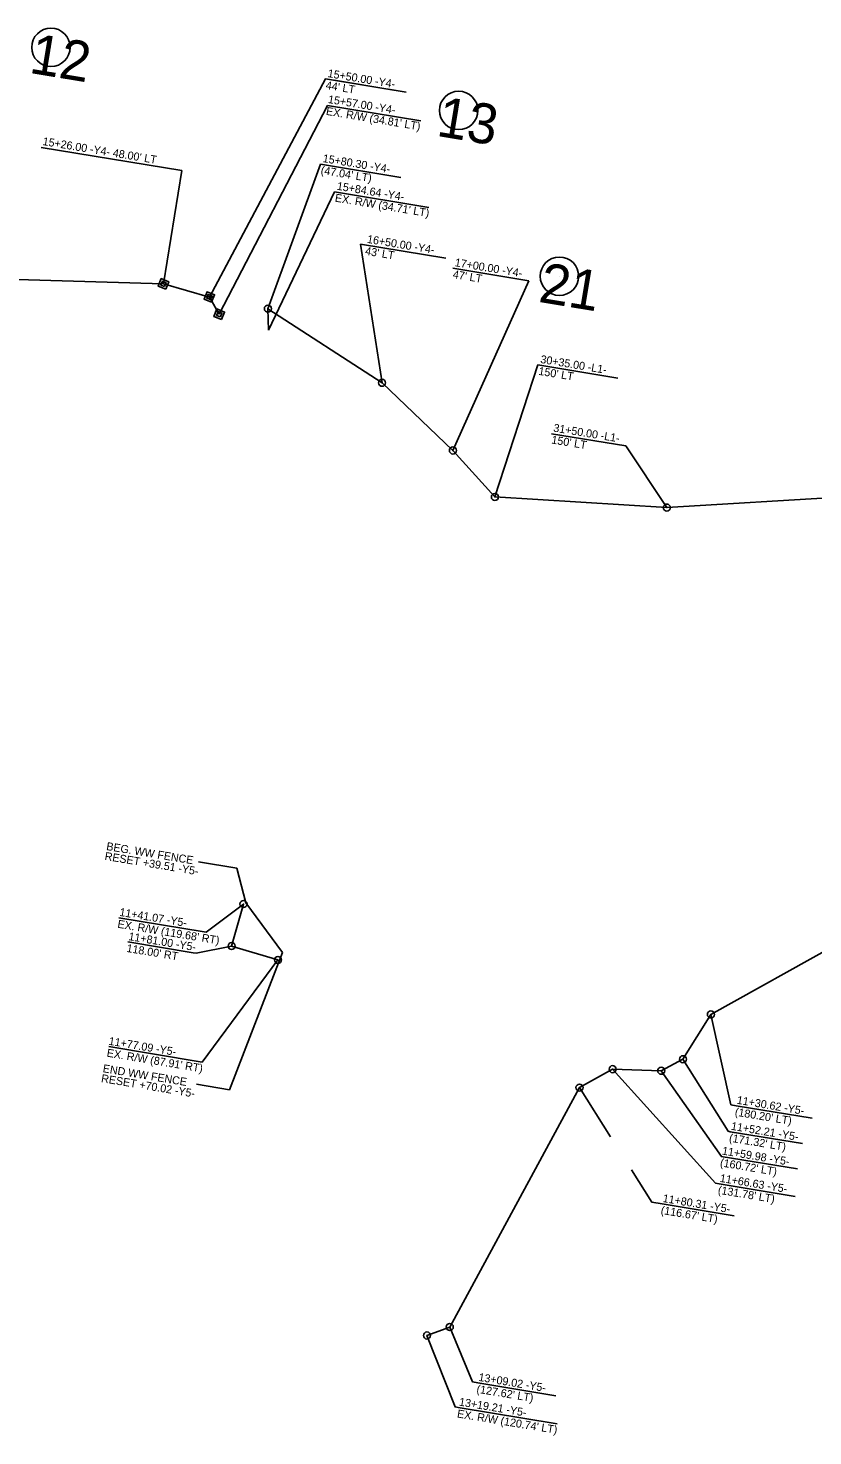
# Model space of a CAD drawing. Extents: x 2175623 to 2194100, y 76458 to 87202.
# Drawn here: x 2192684 to 2193175, y 86276 to 87155 of the extents above; entities that cross this region are included whole.
import ezdxf

# ---------------------------------------------------------------- set-up
doc = ezdxf.new("R2010")
doc.units = 0
for name, color, linetype in [('Exist Property Iron Pin CELL', 7, 'Continuous'), ('Prop Drainage Structure Box Number Symbol CELL', 7, 'Continuous'), ('Prop Drainage Structure Headwall CELL', 7, 'Continuous'), ('Prop Drainage Structure Pipe RCP 36in Class IV', 7, 'Continuous'), ('Prop Drainage Structure Pipe RCP 42in Class IV', 7, 'Continuous'), ('Prop Drainage Structure Pipe RCP 60in Class IV', 7, 'Continuous'), ('Prop Drainage Structure Pipe Removal Label', 7, 'Continuous'), ('Prop Drainage Structure Plot Symbol 50 Scale', 7, 'Continuous'), ('Prop Earthen Structure Base Ditch Special Lateral Detail Label', 7, 'Continuous'), ('Prop Erosion Rip Rap Pad at Outlet Label', 7, 'Continuous'), ('Prop Plan Preparation Crest Label', 7, 'Continuous'), ('Prop Plan Preparation Sag Label', 7, 'Continuous'), ('Scratch_Level_3', 7, 'Continuous')]:
    doc.layers.add(name, color=color, linetype=linetype)

# ---------------------------------------------------------------- blocks, each defined once
blk = doc.blocks.new('ROW Marker Permanent Easement-E')
at = {"layer": 'Prop Earthen Structure Base Ditch Special Lateral Detail Label'}
for points in [[(0, 0.072), (0.072, 0), (0, -0.072), (-0.072, 0)], [(0, 0.036), (0.036, 0), (0, -0.036), (-0.036, 0)]]:
    blk.add_lwpolyline(points, close=True, dxfattribs=at)
at = {"layer": 'Prop Plan Preparation Crest Label'}
blk.add_line((0, 0), (0, 0), dxfattribs=at)

msp = doc.modelspace()

# ---------------------------------------------------------------- linework, layer by layer
at = {"layer": 'Exist Property Iron Pin CELL'}
for centre, radius in [((2192834.02, 86980.16), 2.2), ((2192834.02, 86980.16), 0.0707), ((2192905.37, 86933.87), 2.2), ((2192905.37, 86933.87), 0.0707), ((2192949.62, 86891.57), 2.2), ((2192949.62, 86891.57), 0.0707), ((2192975.84, 86862.52), 2.2), ((2192975.84, 86862.52), 0.0707), ((2193083.29, 86855.91), 2.2), ((2193083.29, 86855.91), 0.0707), ((2192818.79, 86608.21), 2.2), ((2192818.79, 86608.21), 0.0707), ((2192811.36, 86581.93), 2.2), ((2192811.36, 86581.93), 0.0707), ((2192840.31, 86573.26), 2.2), ((2192840.31, 86573.26), 0.0707), ((2193110.8, 86539.2), 2.2), ((2193110.8, 86539.2), 0.0707), ((2193093.38, 86511.25), 2.2), ((2193093.38, 86511.25), 0.0707), ((2193049.41, 86505.02), 2.2), ((2193049.41, 86505.02), 0.0707), ((2193079.77, 86504), 2.2), ((2193079.77, 86504), 0.0707), ((2193028.73, 86493.51), 2.2), ((2193028.73, 86493.51), 0.0707), ((2192947.69, 86343.91), 2.2), ((2192947.69, 86343.91), 0.0707), ((2192933.44, 86338.61), 2.2), ((2192933.44, 86338.61), 0.0707)]:
    msp.add_circle(centre, radius, dxfattribs=at)
at = {"layer": 'Prop Drainage Structure Box Number Symbol CELL'}
for p, q in [((2192698.47, 87143.44), (2192698.47, 87143.44)), ((2192953.24, 87104.02), (2192953.24, 87104.02)), ((2193016.2, 87000.44), (2193016.2, 87000.44))]:
    msp.add_line(p, q, dxfattribs=at)
for centre in [(2192698.47, 87143.44), (2192953.24, 87104.02), (2193016.2, 87000.44)]:
    msp.add_circle(centre, 12, dxfattribs=at)
at = {"layer": 'Prop Drainage Structure Headwall CELL'}
for p, q in [((2192912.8, 87116.74), (2192875.39, 87122.94)), ((2192803.63, 86976.67), (2192871.23, 87107.21)), ((2192929.62, 87097.54), (2192871.23, 87107.21)), ((2192780.26, 87066.4), (2192692.37, 87080.97))]:
    msp.add_line(p, q, dxfattribs=at)
for points in [[(2192920.43, 87115.48), (2192870.05, 87123.83), (2192797.46, 86987.46)], [(2192692.37, 87080.97), (2192780.26, 87066.4), (2192768.82, 86995.61)]]:
    msp.add_lwpolyline(points, dxfattribs=at)
at = {"layer": 'Prop Drainage Structure Pipe RCP 36in Class IV'}
for p, q in [((2192834.02, 86980.16), (2192866.85, 87070.48)), ((2192866.85, 87070.48), (2192917.03, 87062.17)), ((2192834.5, 86966.77), (2192875.68, 87053.18)), ((2192875.68, 87053.18), (2192934.6, 87043.42)), ((2192891.89, 87020.46), (2192945.19, 87011.63)), ((2192905.37, 86933.87), (2192891.89, 87020.46)), ((2192949.56, 87005.38), (2192997.1, 86997.5)), ((2192949.62, 86891.57), (2192997.1, 86997.5)), ((2192975.84, 86862.52), (2193002.6, 86945)), ((2193052.71, 86936.7), (2193002.6, 86945)), ((2193057.66, 86894.43), (2193011.27, 86902.02)), ((2193083.29, 86855.91), (2193057.66, 86894.43)), ((2193174.09, 86474.35), (2193126.55, 86482.21)), ((2193168.13, 86458.49), (2193122.95, 86465.96)), ((2193164.86, 86442.65), (2193117.31, 86450.52)), ((2193163.49, 86425.55), (2193115.95, 86433.41)), ((2193125.45, 86413.34), (2193080.27, 86420.81)), ((2193013.87, 86301), (2192965.15, 86309.07)), ((2193014.7, 86283.43), (2192952.99, 86293.65))]:
    msp.add_line(p, q, dxfattribs=at)
for points in [[(2193126.55, 86482.21), (2193123.29, 86482.75), (2193110.8, 86539.2)], [(2193122.95, 86465.96), (2193121.54, 86466.2), (2193093.38, 86511.25)], [(2193115.95, 86433.41), (2193113.6, 86433.8), (2193049.41, 86505.02)], [(2193117.31, 86450.52), (2193117.49, 86450.49), (2193079.77, 86504)], [(2193048.1, 86462.81), (2193028.73, 86493.51)], [(2193080.27, 86420.81), (2193073.92, 86421.86), (2193061.13, 86442.15)], [(2192965.15, 86309.07), (2192961.89, 86309.61), (2192947.69, 86343.91)], [(2192952.99, 86293.65), (2192950.97, 86293.99), (2192933.44, 86338.61)]]:
    msp.add_lwpolyline(points, dxfattribs=at)
at = {"layer": 'Prop Drainage Structure Pipe RCP 42in Class IV'}
for p, q in [((2192818.79, 86608.21), (2192811.36, 86581.93)), ((2192811.36, 86581.93), (2192840.31, 86573.26))]:
    msp.add_line(p, q, dxfattribs=at)
at = {"layer": 'Prop Drainage Structure Pipe RCP 60in Class IV'}
for p, q in [((2192794.17, 86590.79), (2192740.81, 86599.63)), ((2192787.42, 86577.7), (2192746.5, 86584.48)), ((2192791.68, 86509.68), (2192734.6, 86519.14))]:
    msp.add_line(p, q, dxfattribs=at)
for points in [[(2192794.17, 86590.79), (2192795.48, 86590.57), (2192818.79, 86608.21)], [(2192787.42, 86577.7), (2192789.13, 86577.42), (2192811.36, 86581.93)], [(2192791.68, 86509.68), (2192792.96, 86509.46), (2192840.31, 86573.26)]]:
    msp.add_lwpolyline(points, dxfattribs=at)
at = {"layer": 'Prop Drainage Structure Pipe Removal Label'}
for p, q in [((2192814.59, 86630.64), (2192790.68, 86634.61)), ((2192820.2, 86608.91), (2192814.59, 86630.64)), ((2192843.22, 86577.94), (2192810.12, 86492.12)), ((2192810.12, 86492.12), (2192789.43, 86495.55))]:
    msp.add_line(p, q, dxfattribs=at)
at = {"layer": 'Prop Drainage Structure Plot Symbol 50 Scale'}
for p, q in [((2192677.31, 86998.39), (2192768.82, 86995.61)), ((2192768.82, 86995.61), (2192797.46, 86987.46)), ((2192797.46, 86987.46), (2192803.63, 86976.67))]:
    msp.add_line(p, q, dxfattribs=at)
at = {"layer": 'Prop Plan Preparation Sag Label'}
for p, q in [((2192834.02, 86980.16), (2192905.37, 86933.87)), ((2192834.5, 86966.77), (2192834.02, 86980.16)), ((2192905.37, 86933.87), (2192949.62, 86891.57)), ((2192949.62, 86891.57), (2192975.84, 86862.52)), ((2192975.84, 86862.52), (2193083.29, 86855.91)), ((2193083.29, 86855.91), (2193237.41, 86865.08)), ((2193110.8, 86539.2), (2193189.2, 86582.84)), ((2193093.38, 86511.25), (2193110.8, 86539.2)), ((2193079.77, 86504), (2193093.38, 86511.25)), ((2193028.73, 86493.51), (2193049.41, 86505.02)), ((2193049.41, 86505.02), (2193079.77, 86504)), ((2192947.69, 86343.91), (2193028.73, 86493.51)), ((2192933.44, 86338.61), (2192947.69, 86343.91))]:
    msp.add_line(p, q, dxfattribs=at)
at = {"layer": 'Scratch_Level_3'}
msp.add_line((2192820.2, 86608.91), (2192843.22, 86577.94), dxfattribs=at)

# ---------------------------------------------------------------- block references
at = {"layer": 'Prop Plan Preparation Sag Label', "xscale": 49.99999999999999, "yscale": 50.00000000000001, "rotation": -156.87942851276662}
for p in [(2192768.82, 86995.61), (2192797.46, 86987.46), (2192803.63, 86976.67)]:
    msp.add_blockref('ROW Marker Permanent Easement-E', p, dxfattribs=at)

# ---------------------------------------------------------------- texts
at = {"layer": 'Prop Drainage Structure Headwall CELL'}
for s, p in [('15+50.00 -Y4-', (2192871.12, 87124.92)), ("44' LT", (2192869.9, 87117.52)), ('15+57.00 -Y4- ', (2192871.33, 87108.73)), ("EX. R/W (34.81' LT)", (2192870.1, 87101.33)), ("15+26.00 -Y4- 48.00' LT", (2192693.03, 87082.46))]:
    msp.add_text(s, height=5, rotation=350.59168, dxfattribs=at).set_placement(p)
at = {"layer": 'Prop Drainage Structure Pipe RCP 36in Class IV'}
for s, rotation, p in [('15+80.30 -Y4- ', 350.59168, (2192868.04, 87071.82)), ("(47.04' LT)", 350.59168, (2192866.81, 87064.42)), ('15+84.64 -Y4- ', 350.59168, (2192876.87, 87054.52)), ("EX. R/W (34.71' LT)", 350.59168, (2192875.64, 87047.12)), ('16+50.00 -Y4- ', 350.59168, (2192895.73, 87021.35)), ("43' LT", 350.59168, (2192894.51, 87013.95)), ('17+00.00 -Y4- ', 350.59168, (2192950.54, 87006.75)), ("47' LT", 350.59168, (2192949.31, 86999.35)), ('30+35.00 -L1- ', 350.59168, (2193004.04, 86946.3)), ("150' LT", 350.59168, (2193002.82, 86938.9)), ('31+50.00 -L1- ', 350.71119, (2193012.13, 86903.4)), ("150' LT", 350.71119, (2193010.92, 86896)), ('11+30.62 -Y5-', 350.6062, (2193126.75, 86483.45)), ("(180.20' LT)", 350.6062, (2193125.53, 86476.05)), ('11+52.21 -Y5-', 350.6062, (2193123.15, 86467.2)), ("(171.32' LT)", 350.6062, (2193121.93, 86459.8)), ("(160.72' LT)", 350.6062, (2193116.29, 86444.35)), ('11+59.98 -Y5-', 350.6062, (2193117.52, 86451.75)), ("(131.78' LT)", 350.6062, (2193114.93, 86427.25)), ('11+66.63 -Y5-', 350.6062, (2193116.15, 86434.65)), ('11+80.31 -Y5-', 350.6062, (2193080.47, 86422.05)), ("(116.67' LT)", 350.6062, (2193079.25, 86414.65)), ("(127.62' LT)", 350.59168, (2192964.13, 86302.91)), ('13+09.02 -Y5-', 350.59168, (2192965.35, 86310.3)), ('13+19.21 -Y5-', 350.59168, (2192953.2, 86294.89)), ("EX. R/W (120.74' LT)", 350.59168, (2192951.97, 86287.49))]:
    msp.add_text(s, height=5, rotation=rotation, dxfattribs=at).set_placement(p)
at = {"layer": 'Prop Drainage Structure Pipe RCP 60in Class IV'}
for s, p in [("EX. R/W (119.68' RT)", (2192739.79, 86593.46)), ('11+41.07 -Y5-', (2192741.02, 86600.86)), ('11+81.00 -Y5-', (2192746.7, 86585.72)), ("118.00' RT", (2192745.47, 86578.32)), ('11+77.09 -Y5-', (2192734.31, 86520.31)), ("EX. R/W (87.91' RT)", (2192733.08, 86512.91))]:
    msp.add_text(s, height=5, rotation=350.59168, dxfattribs=at).set_placement(p)
at = {"layer": 'Prop Drainage Structure Pipe Removal Label'}
for s, p in [('BEG. WW FENCE', (2192732.81, 86642)), ('RESET +39.51 -Y5-', (2192731.79, 86635.83)), ('RESET +70.02 -Y5-', (2192729.59, 86497)), ('END WW FENCE', (2192730.62, 86503.17))]:
    msp.add_text(s, height=5, rotation=350.59168, dxfattribs=at).set_placement(p)
at = {"layer": 'Prop Erosion Rip Rap Pad at Outlet Label'}
for s, p in [('12', (2192684.29, 87127.6)), ('13', (2192938.75, 87088.23)), ('21', (2193002.5, 86984.52))]:
    msp.add_text(s, height=25, rotation=350.59168, dxfattribs=at).set_placement(p)

doc.saveas('drawing.dxf')
